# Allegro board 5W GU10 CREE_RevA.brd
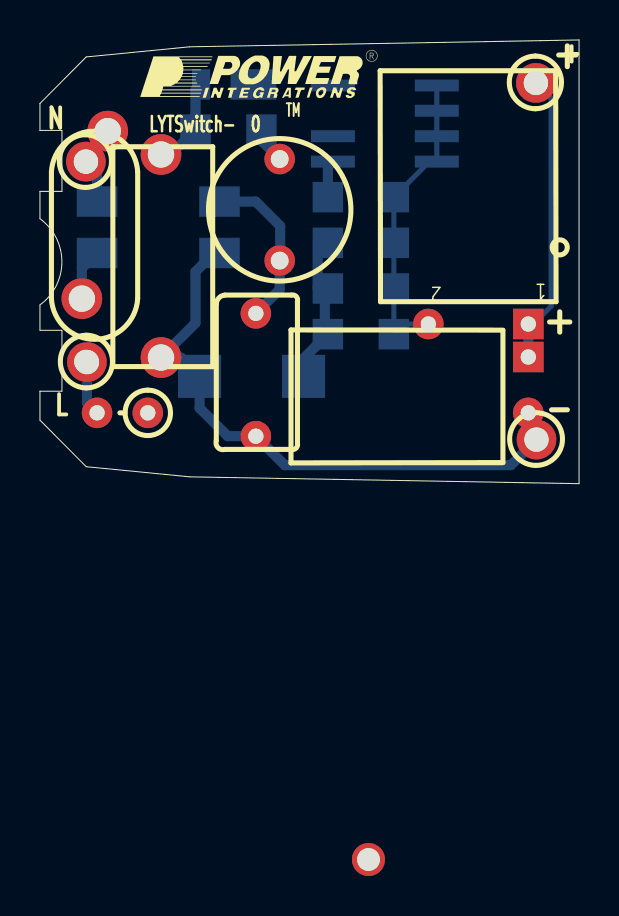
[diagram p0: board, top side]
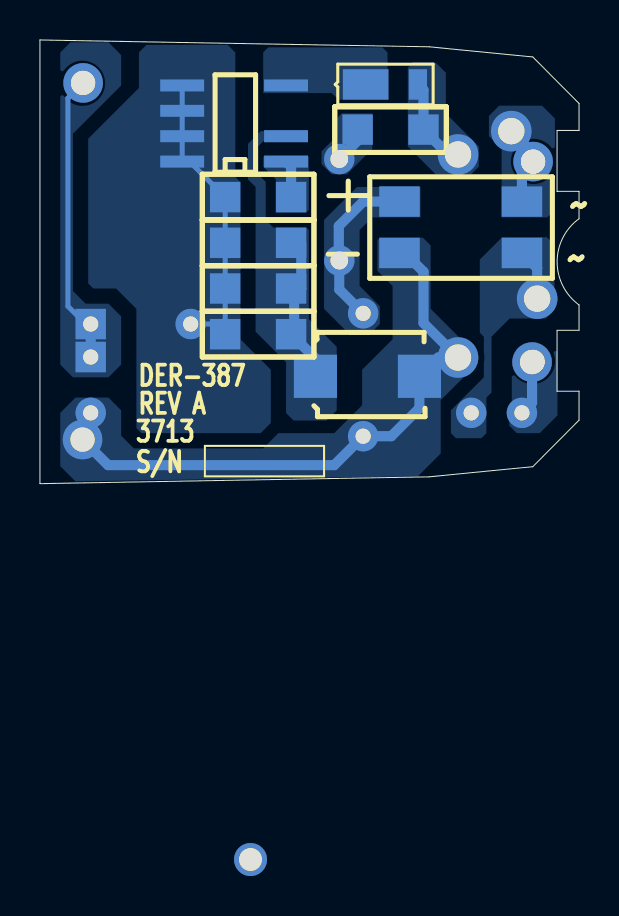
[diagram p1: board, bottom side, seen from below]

Outline 26.99 x 22.2 mm; copper layers: TOP, BOTTOM. Coordinates in mm from the lower left corner of the outline.
Outline path: circle c2.3,16.11 r0.57 ; circle c2.3,16.11 r0.57 ; circle c2.3,6.11 r0.57 ; 0,13.26 arc(1.1,11.1) 0,8.94 ; 0,13.26 0,14.63 1.1,14.63 1.1,17.67 0,17.67 0,19.03 2.32,21.35 7.5,21.86 26.99,22.2 26.99,0 7.5,0.34 2.32,0.85 0,3.18 0,4.63 1.1,4.63 1.1,7.67 0,7.67 0,8.94

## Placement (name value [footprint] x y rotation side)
BR1  MB6S  [PISMSOIC4]  2.86 11.54 90 bottom
C1  47 nF  [PI_NP_CAPRAD315X170LS200D030]  10.86 3.04 90 top
C2  470 nF  [PINPCAPRAD500X240400040]  6.04 16.5 270 top
C3  100 nF  [PISMC1206]  14.42 14.34 0 bottom
C4  22 uF  [PISMC1206]  14.42 12.05 0 bottom
C5  56 uF  [PIPOLCAPCYLD250LS100030]  25.14 5.3 270 top
D1  MURS160T3G  [PISMSMB]  13.2 5.37 180 bottom
D2  DFLU1400-7  [PISMDDFLR120012]  10.71 19.98 0 bottom
F1  3 A  [PIVAXIALD100LS100030]  5.4 3.54 180 top
J1  PCB Terminal 22 AWG  [PI_HOLE_22AWG]  2.35 6.08 0 top
J2  PCB Terminal 22 AWG  [PI_HOLE_22AWG]  2.3 16.12 0 top
J3  PCB Terminal 22 AWG  [PI_HOLE_22AWG]  24.83 20.05 0 top
J4  PCB Terminal 22 AWG  [PI_HOLE_22AWG]  24.86 2.21 0 top
L1  2.2 mH  [PICHOKE030DIALS200035]  12 11.16 90 top
L2  1.5 mH  [PI_CHOKE_450HX375LS197D030]  24.45 7.99 180 top
NOREF  -  [unnamed]  18.59 -11 180 top
NOREF#2  -  [#2]  26.99 0 90 top
NOREF#3  -  [#2]  -224.85 -142.38 0 top
NOREF#4  -  [#2]  5.02 19.29 0 top
NOREF#5  -  [#2]  0 19.03 0 top
NOREF#6  -  [#2]  -147.04 56.63 0 top
R1  10  [PISMR1206]  11.09 17.72 180 bottom
R2  30.1  [PISMR1206]  17.72 9.77 180 bottom
R3  30.1  [PISMR1206]  17.72 7.48 180 bottom
RV1  140 Vac  [PINPCAPRAD370X156250040]  3.37 15.61 270 top
U1  LYT0006DN  [PIICSMDSO8]  14.67 16.12 90 bottom

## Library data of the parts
BR1 = DIODE BRIDGE_~~+-_0: alternate symbols: (pi_sm_soic4_slot)
C1-C4 = CAP NP
C5 = CAP POL: alternate symbols: (pipolcapcyld250ls100030h)
D1 D2 = DIODE
F1 = FUSE
J1-J4 = TERM_1PIN
L1 = INDUCTOR
L2 = INDUCTOR1-2
R1-R3 = R
RV1 = VARISTOR
U1 = LNK30X_SO8_DN_1

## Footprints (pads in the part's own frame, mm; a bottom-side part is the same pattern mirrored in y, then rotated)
PI_CHOKE_450HX375LS197D030
  rect 1.524x1.524 hole 0.762: 1(0,0)
  round 1.524 hole 0.762: 2(5.004,0)
PI_HOLE_22AWG
  round 1.981 hole 1.219: 1(0,0)
PI_NP_CAPRAD315X170LS200D030
  round 1.524 hole 0.762: 1(-0.66,0.051) 2(5.486,0.051)
PICHOKE030DIALS200035
  round 1.524 hole 0.889: 1(0,0) 2(5.08,0)
PIICSMDSO8
  rect 0.599x2.2 smd: 1(0,0) 2(1.27,0) 4(3.81,0) 5(3.81,5.199) 6(2.54,5.199) 7(1.27,5.199) 8(0,5.199)
PINPCAPRAD370X156250040
  round 2.032 hole 1.321: 1(-2.032,0.025) 2(6.35,-1.27)
PINPCAPRAD500X240400040
  round 2.032 hole 1.321: 1(0.025,0.025) 2(10.185,0.025)
PIPOLCAPCYLD250LS100030
  rect 1.524x1.524 hole 0.762: 1(-1.041,-0.686)
  round 1.524 hole 0.762: 2(1.753,-0.686)
PISMC1206
  rect 1.524x1.524 smd: 1(0,0) 2(3.302,0)
PISMDDFLR120012
  rect 2.286x1.524 smd: 1(-0.025,0)
  rect 0.914x1.524 smd: 2(-2.642,0)
PISMR1206
  rect 1.524x1.524 smd: 1(0,0) 2(3.302,0)
PISMSMB
  rect 2.159x2.159 smd: 1(0,0) 2(5.207,0)
PISMSOIC4
  rect 1.524x2.032 smd: 1(0,0) 2(2.571,0) 3(2.571,6.129) 4(0,6.129)
PIVAXIALD100LS100030
  round 1.524 hole 0.762: 1(0,0) 2(2.54,0)
unnamed
  round 1.651 hole 1.143: 1(-6.274,-31.039) 2(2.137,7.807) 3(16.307,-27.127) 4(16.256,-17.12)

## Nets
S: C3.2 C4.2 L2.2 R2.1 R3.1 U1.5(S) U1.6 U1.7 U1.8
N00373: BR1.3 C1.2 L1.1
N00556: BR1.4 C1.1 C2.2 C5.2 D1.2 J4.1
N00722: BR1.2 J2.1 RV1.1
N00762: C4.1 D1.1 R2.2 R3.2 U1.2(FB)
N08431: BR1.1 F1.1 RV1.2
N09054: F1.2 J1.1
N44848: C3.1 U1.1(BP)
N45009: C2.1 D2.2 R1.2
N47034: D2.1 U1.4(D)
N50424: C5.1 J3.1 L2.1
N52058: L1.2 R1.1

Pads without a net: NOREF 1 2 3 4

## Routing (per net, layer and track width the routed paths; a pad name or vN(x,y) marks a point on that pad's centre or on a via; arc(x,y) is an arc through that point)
S: length 15.5
  BOTTOM w0.254: U1.5 U1.6 U1.7 U1.8 19.5,16.12 C3.2 C4.2 R2.1 R3.1 18.23,7.99 L2.2
N00373: length 8.4
  BOTTOM w0.508: C1.2 12,9.72 L1.1 12.03,11.19 12.03,12.89 10.81,14.12 BR1.3
N00556: length 30.6
  BOTTOM w0.508: C5.2 24.45,2.62 J4.1 23.58,0.93 12.26,0.93 C1.1 9.4,2.38 7.99,3.79 D1.2 7.05,6.31 C2.2 6.4,6.66 6.4,6.66 6.7,6.96 6.71,6.96 7.79,8.04 7.79,10.61 8.73,11.54 BR1.4
N00722: length 4.2
  BOTTOM w0.508: BR1.2 2.86,15.56 J2.1 2.3,16.55 RV1.1
N00762: length 9
  BOTTOM w0.254: 13.91,12.05 C4.1 ; 15.43,17.39 U1.2 14.16,17.39
  BOTTOM w0.508: 13.91,12.05 13.91,9.77 14.27,9.41 14.27,7.61 ; R3.2 13.2,6.26 D1.1
N08431: length 2.6
  BOTTOM w0.508: BR1.1 2.1,10.78 RV1.2
N09054: length 2.8
  BOTTOM w0.508: J1.1 2.35,4.05 2.86,3.54
N44848: length 1.9
  BOTTOM w0.508: U1.1 14.42,15.86 C3.1
N45009: length 4.6
  BOTTOM w0.508: C2.1 6.54,16.47 R1.2 7.79,19.7 D2.2
N50424: length 14.7
  BOTTOM w0.254: J3.1 25.59,19.29 25.59,8.88 24.7,7.99 L2.1
  BOTTOM w0.508: C5.1 L2.1
N52058: length 1.9
  BOTTOM w0.508: R1.1 11.09,17.16 L1.2

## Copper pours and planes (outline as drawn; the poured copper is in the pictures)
S on BOTTOM: 16.96,15.1 17.21,15.35 17.21,21.58 17.59,21.96 21.66,21.96 22.04,21.58 22.04,19.8 24.58,17.26 24.58,10.02 24.32,9.77 23.18,9.77 22.16,8.75 22.16,2.78 21.91,2.53 15.94,2.53 15.43,3.04 15.43,5.7 16.96,7.23
N00373 on BOTTOM: 7.94,14.85 11.12,14.85 12.77,13.2 12.77,8.75 11.5,7.48 10.48,7.48 9.97,7.99 9.97,8.88 10.99,9.89 10.99,12.69 10.35,13.32 7.94,13.32
N00556 on BOTTOM: 5.27,5.83 5.27,6.59 7.43,8.75 7.43,11.93 7.81,12.31 9.97,12.31 10.1,12.18 10.1,10.66 9.34,9.89 9.34,7.23 10.86,5.7 10.86,3.92 12.26,2.53 15.05,2.53 15.81,1.77 22.29,1.77 22.93,2.4 22.93,3.67 23.56,4.31 25.21,4.31 25.97,3.54 25.97,0.88 25.21,0.11 8.07,0.37 6.92,1.51 6.92,4.18
N00722 on BOTTOM: 1.21,13.7 1.21,18.28 1.84,18.91 4,18.91 4.51,18.4 4.51,17.39 3.88,16.75 3.88,13.32 1.59,13.32
N00762 on BOTTOM: 13.53,12.69 13.66,12.81 15.31,12.81 15.69,13.2 15.69,15.1 16.2,15.61 16.2,16.75 15.81,17.13 13.78,17.13 13.78,17.64 15.94,17.64 16.58,17.01 16.58,15.23 16.2,14.85 16.2,7.61 14.67,6.08 14.67,3.54 14.29,3.16 12.64,3.16 12.13,3.67 12.13,6.85 13.53,8.24
N08431 on BOTTOM: 4.64,2.53 4.64,4.31 4.38,4.56 4.38,7.35 3.47,8.27 1.67,8.27 1.23,8.7 1.23,11.95 1.62,12.33 3.85,12.33 4.97,11.21 4.97,7.56 4.77,7.35 4.77,5.32 6.42,3.67 6.42,2.53 6.16,2.27 4.89,2.27
N09054 on BOTTOM: 2.86,7.1 1.59,7.1 1.08,6.59 1.08,3.42 1.97,2.53 3.11,2.53 3.5,2.91 3.5,3.8 3.37,3.92 3.37,6.59
N44848 on BOTTOM: 13.53,16.37 13.53,13.7 13.66,13.58 15.18,13.58 15.18,15.23 15.81,15.86 15.81,16.37
N45009 on BOTTOM: 8.58,16.88 8.58,20.82 8.32,21.07 7.18,21.07 6.67,20.56 6.67,18.53 5.02,16.88 5.02,15.86 5.4,15.48 7.18,15.48
N47034 on BOTTOM: 9.59,19.22 9.59,21.58 9.85,21.83 15.56,21.83 15.81,21.58 15.81,19.55 12.39,19.55 12.03,19.22
N50424 on BOTTOM: 22.93,5.96 22.93,8.37 23.56,9 24.7,9 25.34,9.64 25.34,17.51 22.93,19.93 22.93,21.45 23.56,22.09 25.47,22.09 25.97,21.58 25.97,5.96 25.34,5.32 23.56,5.32
N52058 on BOTTOM: 10.35,18.53 10.35,16.75 11.62,15.48 12.39,15.48 12.89,15.99 12.89,16.62 12.13,17.39 12.13,18.28 11.88,18.53

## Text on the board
Ref Des/Silkscreen Bottom: DER-387 | REV A | 3713 | S/N
Ref Des/Assembly Top: RAIL KEEP OFF AREA 35 MIL
Ref Des/Silkscreen Top: TM | LYTSwitch-  0 | N | L | +
PEN17: PLEASE DELETE THESE PINS | 13   MATERIAL FR4 COPPER 2oz THICKNESS 0.031"
User.5: FIGURE | SIZE | 30.0 | 35.0 | 45.0 | 48.0 | 52.0 | DRILL CHART: TOP to BOTTOM | ALL UNITS ARE IN MILS | PLATED | QTY | 8 | 2 | 4
